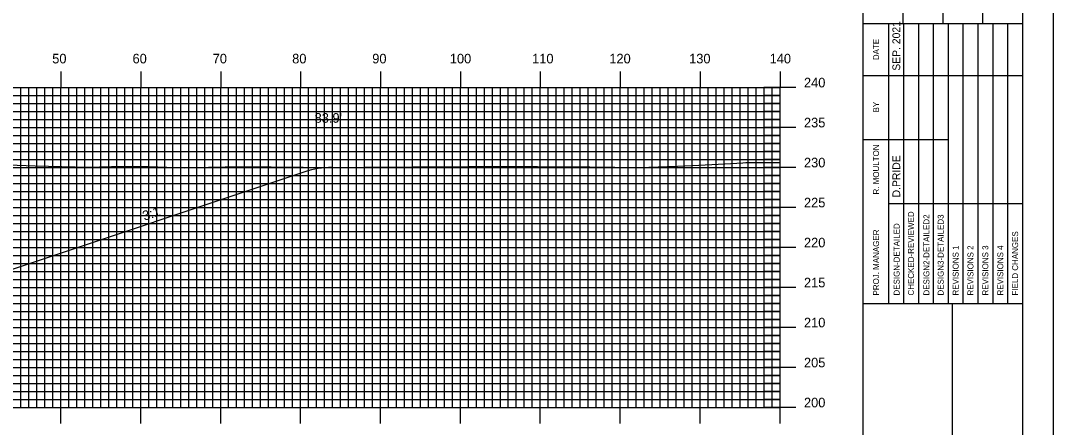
# Model space of a CAD drawing. Extents: x 1801536 to 1801879, y 442591 to 442811.
# Drawn here: x 1801746.5 to 1801875.8, y 442671.2 to 442722 of the extents above; entities that cross this region are included whole.
import ezdxf

# ---------------------------------------------------------------- set-up
doc = ezdxf.new("R2010")
doc.units = 0
for name, color, linetype in [('ANNOTATION', 7, 'Continuous'), ('BORDER', 7, 'Continuous'), ('D_Roadway_SlopeLines', 7, 'Continuous'), ('D_Text_Standard', 7, 'Continuous'), ('H_V ANNOTATION', 7, 'Continuous'), ('MAJOR', 7, 'Continuous'), ('MINOR', 7, 'Continuous'), ('PLOT BOUNDARY', 7, 'Continuous'), ('S_Roadway_Centerline', 7, 'Continuous')]:
    doc.layers.add(name, color=color, linetype=linetype)

msp = doc.modelspace()

# ---------------------------------------------------------------- linework, layer by layer
at = {"layer": 'BORDER'}
for p, q in [((1801851.98, 442596.67), (1801851.98, 442806.67)), ((1801856.98, 442721.67), (1801856.98, 442738.97)), ((1801861.98, 442721.67), (1801861.98, 442738.97)), ((1801866.98, 442721.67), (1801866.98, 442738.97)), ((1801851.98, 442721.67), (1801871.98, 442721.67)), ((1801851.98, 442686.67), (1801871.98, 442686.67)), ((1801863.16, 442616.67), (1801863.16, 442686.67))]:
    msp.add_line(p, q, dxfattribs=at)
msp.add_lwpolyline([(1801551.98, 442596.67), (1801871.98, 442596.67), (1801871.98, 442806.67), (1801551.98, 442806.67)], close=True, dxfattribs=at)
for points in [[(1801855.21, 442715.17), (1801855.21, 442721.67)], [(1801857.07, 442686.68), (1801857.07, 442721.67)], [(1801858.93, 442721.67), (1801858.93, 442686.68)], [(1801860.8, 442686.68), (1801860.8, 442721.67)], [(1801862.66, 442686.68), (1801862.66, 442721.67)], [(1801864.52, 442686.68), (1801864.52, 442721.67)], [(1801866.39, 442686.68), (1801866.39, 442721.67)], [(1801868.25, 442686.68), (1801868.25, 442721.67)], [(1801870.11, 442686.68), (1801870.11, 442721.67)], [(1801855.21, 442686.68), (1801855.21, 442720.26)], [(1801851.98, 442715.17), (1801871.98, 442715.17)], [(1801851.98, 442707.17), (1801855.21, 442707.17)], [(1801855.21, 442707.17), (1801862.66, 442707.17)], [(1801855.21, 442699.17), (1801871.98, 442699.17)]]:
    msp.add_lwpolyline(points, dxfattribs=at)
at = {"layer": 'D_Roadway_SlopeLines'}
msp.add_line((1801782.1, 442703.11), (1801744.37, 442690.54), dxfattribs=at)
msp.add_arc((1801785.54, 442692.77), 10.9, 90.1703, 108.4349, dxfattribs=at)
at = {"layer": 'MAJOR'}
for p, q in [((1801751.58, 442715.67), (1801751.58, 442713.67)), ((1801761.58, 442715.67), (1801761.58, 442713.67)), ((1801771.58, 442715.67), (1801771.58, 442713.67)), ((1801781.58, 442715.67), (1801781.58, 442713.67)), ((1801791.58, 442715.67), (1801791.58, 442713.67)), ((1801801.58, 442715.67), (1801801.58, 442713.67)), ((1801811.58, 442715.67), (1801811.58, 442713.67)), ((1801821.58, 442715.67), (1801821.58, 442713.67)), ((1801831.58, 442715.67), (1801831.58, 442713.67)), ((1801841.58, 442715.67), (1801841.58, 442713.67)), ((1801561.58, 442713.67), (1801841.58, 442713.67)), ((1801561.58, 442713.67), (1801841.58, 442713.67)), ((1801751.58, 442673.67), (1801751.58, 442713.67)), ((1801761.58, 442673.67), (1801761.58, 442713.67)), ((1801771.58, 442673.67), (1801771.58, 442713.67)), ((1801781.58, 442673.67), (1801781.58, 442713.67)), ((1801791.58, 442673.67), (1801791.58, 442713.67)), ((1801801.58, 442673.67), (1801801.58, 442713.67)), ((1801811.58, 442673.67), (1801811.58, 442713.67)), ((1801821.58, 442673.67), (1801821.58, 442713.67)), ((1801831.58, 442673.67), (1801831.58, 442713.67)), ((1801843.58, 442713.67), (1801839.57, 442713.67)), ((1801841.58, 442673.67), (1801841.58, 442713.67)), ((1801841.58, 442673.67), (1801841.58, 442713.67)), ((1801561.58, 442708.67), (1801841.58, 442708.67)), ((1801843.58, 442708.67), (1801839.57, 442708.67)), ((1801561.58, 442703.67), (1801841.58, 442703.67)), ((1801843.58, 442703.67), (1801839.57, 442703.67)), ((1801561.58, 442698.67), (1801841.58, 442698.67)), ((1801843.58, 442698.67), (1801839.57, 442698.67)), ((1801561.58, 442693.67), (1801841.58, 442693.67)), ((1801843.58, 442693.67), (1801839.57, 442693.67)), ((1801561.58, 442688.67), (1801841.58, 442688.67)), ((1801843.58, 442688.67), (1801839.57, 442688.67)), ((1801561.58, 442683.67), (1801841.58, 442683.67)), ((1801843.58, 442683.67), (1801839.57, 442683.67)), ((1801561.58, 442678.67), (1801841.58, 442678.67)), ((1801843.58, 442678.67), (1801839.57, 442678.67)), ((1801561.58, 442673.67), (1801841.58, 442673.67)), ((1801561.58, 442673.67), (1801841.58, 442673.67)), ((1801751.58, 442671.66), (1801751.58, 442673.67)), ((1801761.58, 442671.66), (1801761.58, 442673.67)), ((1801771.58, 442671.66), (1801771.58, 442673.67)), ((1801781.58, 442671.66), (1801781.58, 442673.67)), ((1801791.58, 442671.66), (1801791.58, 442673.67)), ((1801801.58, 442671.66), (1801801.58, 442673.67)), ((1801811.58, 442671.66), (1801811.58, 442673.67)), ((1801821.58, 442671.66), (1801821.58, 442673.67)), ((1801831.58, 442671.66), (1801831.58, 442673.67)), ((1801843.58, 442673.67), (1801839.57, 442673.67)), ((1801841.58, 442671.66), (1801841.58, 442673.67))]:
    msp.add_line(p, q, dxfattribs=at)
at = {"layer": 'MINOR'}
for p, q in [((1801746.58, 442673.67), (1801746.58, 442713.67)), ((1801747.58, 442673.67), (1801747.58, 442713.67)), ((1801748.58, 442673.67), (1801748.58, 442713.67)), ((1801749.58, 442673.67), (1801749.58, 442713.67)), ((1801750.58, 442673.67), (1801750.58, 442713.67)), ((1801752.58, 442673.67), (1801752.58, 442713.67)), ((1801753.58, 442673.67), (1801753.58, 442713.67)), ((1801754.58, 442673.67), (1801754.58, 442713.67)), ((1801755.58, 442673.67), (1801755.58, 442713.67)), ((1801756.58, 442673.67), (1801756.58, 442713.67)), ((1801757.58, 442673.67), (1801757.58, 442713.67)), ((1801758.58, 442673.67), (1801758.58, 442713.67)), ((1801759.58, 442673.67), (1801759.58, 442713.67)), ((1801760.58, 442673.67), (1801760.58, 442713.67)), ((1801762.58, 442673.67), (1801762.58, 442713.67)), ((1801763.58, 442673.67), (1801763.58, 442713.67)), ((1801764.58, 442673.67), (1801764.58, 442713.67)), ((1801765.58, 442673.67), (1801765.58, 442713.67)), ((1801766.58, 442673.67), (1801766.58, 442713.67)), ((1801767.58, 442673.67), (1801767.58, 442713.67)), ((1801768.58, 442673.67), (1801768.58, 442713.67)), ((1801769.58, 442673.67), (1801769.58, 442713.67)), ((1801770.58, 442673.67), (1801770.58, 442713.67)), ((1801772.58, 442673.67), (1801772.58, 442713.67)), ((1801773.58, 442673.67), (1801773.58, 442713.67)), ((1801774.58, 442673.67), (1801774.58, 442713.67)), ((1801775.58, 442673.67), (1801775.58, 442713.67)), ((1801776.58, 442673.67), (1801776.58, 442713.67)), ((1801777.58, 442673.67), (1801777.58, 442713.67)), ((1801778.58, 442673.67), (1801778.58, 442713.67)), ((1801779.58, 442673.67), (1801779.58, 442713.67)), ((1801780.58, 442673.67), (1801780.58, 442713.67)), ((1801782.58, 442673.67), (1801782.58, 442713.67)), ((1801783.58, 442673.67), (1801783.58, 442713.67)), ((1801784.58, 442673.67), (1801784.58, 442713.67)), ((1801785.58, 442673.67), (1801785.58, 442713.67)), ((1801786.58, 442673.67), (1801786.58, 442713.67)), ((1801787.58, 442673.67), (1801787.58, 442713.67)), ((1801788.58, 442673.67), (1801788.58, 442713.67)), ((1801789.58, 442673.67), (1801789.58, 442713.67)), ((1801790.58, 442673.67), (1801790.58, 442713.67)), ((1801792.58, 442673.67), (1801792.58, 442713.67)), ((1801793.58, 442673.67), (1801793.58, 442713.67)), ((1801794.58, 442673.67), (1801794.58, 442713.67)), ((1801795.58, 442673.67), (1801795.58, 442713.67)), ((1801796.58, 442673.67), (1801796.58, 442713.67)), ((1801797.58, 442673.67), (1801797.58, 442713.67)), ((1801798.58, 442673.67), (1801798.58, 442713.67)), ((1801799.58, 442673.67), (1801799.58, 442713.67)), ((1801800.58, 442673.67), (1801800.58, 442713.67)), ((1801802.58, 442673.67), (1801802.58, 442713.67)), ((1801803.58, 442673.67), (1801803.58, 442713.67)), ((1801804.58, 442673.67), (1801804.58, 442713.67)), ((1801805.58, 442673.67), (1801805.58, 442713.67)), ((1801806.58, 442673.67), (1801806.58, 442713.67)), ((1801807.58, 442673.67), (1801807.58, 442713.67)), ((1801808.58, 442673.67), (1801808.58, 442713.67)), ((1801809.58, 442673.67), (1801809.58, 442713.67)), ((1801810.58, 442673.67), (1801810.58, 442713.67)), ((1801812.58, 442673.67), (1801812.58, 442713.67)), ((1801813.58, 442673.67), (1801813.58, 442713.67)), ((1801814.58, 442673.67), (1801814.58, 442713.67)), ((1801815.58, 442673.67), (1801815.58, 442713.67)), ((1801816.58, 442673.67), (1801816.58, 442713.67)), ((1801817.58, 442673.67), (1801817.58, 442713.67)), ((1801818.58, 442673.67), (1801818.58, 442713.67)), ((1801819.58, 442673.67), (1801819.58, 442713.67)), ((1801820.58, 442673.67), (1801820.58, 442713.67)), ((1801822.58, 442673.67), (1801822.58, 442713.67)), ((1801823.58, 442673.67), (1801823.58, 442713.67)), ((1801824.58, 442673.67), (1801824.58, 442713.67)), ((1801825.58, 442673.67), (1801825.58, 442713.67)), ((1801826.58, 442673.67), (1801826.58, 442713.67)), ((1801827.58, 442673.67), (1801827.58, 442713.67)), ((1801828.58, 442673.67), (1801828.58, 442713.67)), ((1801829.58, 442673.67), (1801829.58, 442713.67)), ((1801830.58, 442673.67), (1801830.58, 442713.67)), ((1801832.58, 442673.67), (1801832.58, 442713.67)), ((1801833.58, 442673.67), (1801833.58, 442713.67)), ((1801834.58, 442673.67), (1801834.58, 442713.67)), ((1801835.58, 442673.67), (1801835.58, 442713.67)), ((1801836.58, 442673.67), (1801836.58, 442713.67)), ((1801837.58, 442673.67), (1801837.58, 442713.67)), ((1801838.58, 442673.67), (1801838.58, 442713.67)), ((1801839.58, 442673.67), (1801839.58, 442713.67)), ((1801840.58, 442673.67), (1801840.58, 442713.67)), ((1801561.58, 442712.67), (1801841.58, 442712.67)), ((1801841.58, 442712.67), (1801839.57, 442712.67)), ((1801561.58, 442711.67), (1801841.58, 442711.67)), ((1801561.58, 442710.67), (1801841.58, 442710.67)), ((1801841.58, 442711.67), (1801839.57, 442711.67)), ((1801841.58, 442710.67), (1801839.57, 442710.67)), ((1801561.58, 442709.67), (1801841.58, 442709.67)), ((1801841.58, 442709.67), (1801839.57, 442709.67)), ((1801561.58, 442707.67), (1801841.58, 442707.67)), ((1801561.58, 442706.67), (1801841.58, 442706.67)), ((1801841.58, 442707.67), (1801839.57, 442707.67)), ((1801841.58, 442706.67), (1801839.57, 442706.67)), ((1801561.58, 442705.67), (1801841.58, 442705.67)), ((1801841.58, 442705.67), (1801839.57, 442705.67)), ((1801561.58, 442704.67), (1801841.58, 442704.67)), ((1801841.58, 442704.67), (1801839.57, 442704.67)), ((1801561.58, 442702.67), (1801841.58, 442702.67)), ((1801561.58, 442701.67), (1801841.58, 442701.67)), ((1801841.58, 442702.67), (1801839.57, 442702.67)), ((1801841.58, 442701.67), (1801839.57, 442701.67)), ((1801561.58, 442700.67), (1801841.58, 442700.67)), ((1801841.58, 442700.67), (1801839.57, 442700.67)), ((1801561.58, 442699.67), (1801841.58, 442699.67)), ((1801841.58, 442699.67), (1801839.57, 442699.67)), ((1801561.58, 442697.67), (1801841.58, 442697.67)), ((1801841.58, 442697.67), (1801839.57, 442697.67)), ((1801561.58, 442696.67), (1801841.58, 442696.67)), ((1801841.58, 442696.67), (1801839.57, 442696.67)), ((1801561.58, 442695.67), (1801841.58, 442695.67)), ((1801841.58, 442695.67), (1801839.57, 442695.67)), ((1801561.58, 442694.67), (1801841.58, 442694.67)), ((1801841.58, 442694.67), (1801839.57, 442694.67)), ((1801561.58, 442692.67), (1801841.58, 442692.67)), ((1801841.58, 442692.67), (1801839.57, 442692.67)), ((1801561.58, 442691.67), (1801841.58, 442691.67)), ((1801841.58, 442691.67), (1801839.57, 442691.67)), ((1801561.58, 442690.67), (1801841.58, 442690.67)), ((1801841.58, 442690.67), (1801839.57, 442690.67)), ((1801561.58, 442689.67), (1801841.58, 442689.67)), ((1801841.58, 442689.67), (1801839.57, 442689.67)), ((1801561.58, 442687.67), (1801841.58, 442687.67)), ((1801841.58, 442687.67), (1801839.57, 442687.67)), ((1801561.58, 442686.67), (1801841.58, 442686.67)), ((1801841.58, 442686.67), (1801839.57, 442686.67)), ((1801561.58, 442685.67), (1801841.58, 442685.67)), ((1801841.58, 442685.67), (1801839.57, 442685.67)), ((1801561.58, 442684.67), (1801841.58, 442684.67)), ((1801841.58, 442684.67), (1801839.57, 442684.67)), ((1801561.58, 442682.67), (1801841.58, 442682.67)), ((1801841.58, 442682.67), (1801839.57, 442682.67)), ((1801561.58, 442681.67), (1801841.58, 442681.67)), ((1801841.58, 442681.67), (1801839.57, 442681.67)), ((1801561.58, 442680.67), (1801841.58, 442680.67)), ((1801561.58, 442679.67), (1801841.58, 442679.67)), ((1801841.58, 442680.67), (1801839.57, 442680.67)), ((1801841.58, 442679.67), (1801839.57, 442679.67)), ((1801561.58, 442677.67), (1801841.58, 442677.67)), ((1801841.58, 442677.67), (1801839.57, 442677.67)), ((1801561.58, 442676.67), (1801841.58, 442676.67)), ((1801561.58, 442675.67), (1801841.58, 442675.67)), ((1801841.58, 442676.67), (1801839.57, 442676.67)), ((1801841.58, 442675.67), (1801839.57, 442675.67)), ((1801561.58, 442674.67), (1801841.58, 442674.67)), ((1801841.58, 442674.67), (1801839.57, 442674.67))]:
    msp.add_line(p, q, dxfattribs=at)
at = {"layer": 'PLOT BOUNDARY'}
msp.add_lwpolyline([(1801535.79, 442590.55), (1801875.79, 442590.55), (1801875.79, 442810.55), (1801535.79, 442810.55)], close=True, dxfattribs=at)
at = {"layer": 'S_Roadway_Centerline'}
msp.add_lwpolyline([(1801745, 442703.99), (1801748.37, 442703.85), (1801755.02, 442703.71), (1801756.41, 442703.73), (1801757.91, 442703.76), (1801762.64, 442703.78), (1801767.06, 442703.63), (1801768.13, 442703.66), (1801768.74, 442703.66), (1801770.05, 442703.69), (1801772.13, 442703.73), (1801774.47, 442703.76), (1801776.53, 442703.75), (1801777.88, 442703.73), (1801785.9, 442703.67), (1801789.53, 442703.7), (1801795.53, 442703.72), (1801800.35, 442703.75), (1801802.63, 442703.77), (1801805.38, 442703.79), (1801807.58, 442703.81), (1801814.96, 442703.72), (1801817.77, 442703.75), (1801824.09, 442703.65), (1801825.16, 442703.68), (1801827.44, 442703.76), (1801828.76, 442703.81), (1801830.57, 442703.9), (1801834.69, 442704.13), (1801836.92, 442704.24), (1801837.31, 442704.28), (1801841.58, 442704.3)], dxfattribs=at)

# ---------------------------------------------------------------- texts
at = {"layer": 'ANNOTATION'}
msp.add_text('3:1', height=1.2, rotation=18.4349, dxfattribs=at).set_placement((1801762.03, 442696.99))
at = {"layer": 'BORDER'}
for s, height, p in [('SEP. 2021', 0.969, (1801856.62, 442715.76)), ('DATE', 0.743, (1801853.98, 442717.08)), ('BY', 0.743, (1801853.98, 442710.54)), ('R. MOULTON', 0.745, (1801853.98, 442700.28)), ('D.PRIDE', 0.969, (1801856.62, 442699.92)), ('CHECKED-REVIEWED', 0.7455, (1801858.34, 442687.65)), ('DESIGN2-DETAILED2', 0.7455, (1801860.28, 442687.65)), ('DESIGN3-DETAILED3', 0.7455, (1801862.06, 442687.65)), ('DESIGN-DETAILED', 0.7455, (1801856.55, 442687.65)), ('PROJ. MANAGER', 0.7455, (1801853.98, 442687.65)), ('FIELD CHANGES', 0.7455, (1801871.38, 442687.65)), ('REVISIONS 1', 0.7455, (1801863.93, 442687.65)), ('REVISIONS 2', 0.7455, (1801865.79, 442687.65)), ('REVISIONS 3', 0.7455, (1801867.65, 442687.65)), ('REVISIONS 4', 0.7455, (1801869.52, 442687.65))]:
    msp.add_text(s, height=height, rotation=90, dxfattribs=at).set_placement(p)
at = {"layer": 'D_Text_Standard'}
msp.add_text("83.9'", height=1.2, dxfattribs=at).set_placement((1801783.34, 442709.25))
at = {"layer": 'H_V ANNOTATION'}
for s, p in [('50', (1801750.5, 442716.67)), ('60', (1801760.55, 442716.67)), ('70', (1801770.58, 442716.67)), ('80', (1801780.53, 442716.67)), ('90', (1801790.55, 442716.67)), ('100', (1801800.26, 442716.67)), ('110', (1801810.56, 442716.67)), ('120', (1801820.22, 442716.67)), ('130', (1801830.21, 442716.67)), ('140', (1801840.28, 442716.67)), ('240', (1801844.58, 442713.67)), ('235', (1801844.58, 442708.67)), ('230', (1801844.58, 442703.67)), ('225', (1801844.58, 442698.67)), ('220', (1801844.58, 442693.67)), ('215', (1801844.58, 442688.67)), ('210', (1801844.58, 442683.67)), ('205', (1801844.58, 442678.67)), ('200', (1801844.58, 442673.67))]:
    msp.add_text(s, height=1.2, dxfattribs=at).set_placement(p)

doc.saveas('drawing.dxf')
